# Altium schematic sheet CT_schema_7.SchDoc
size 254 x 194 mm
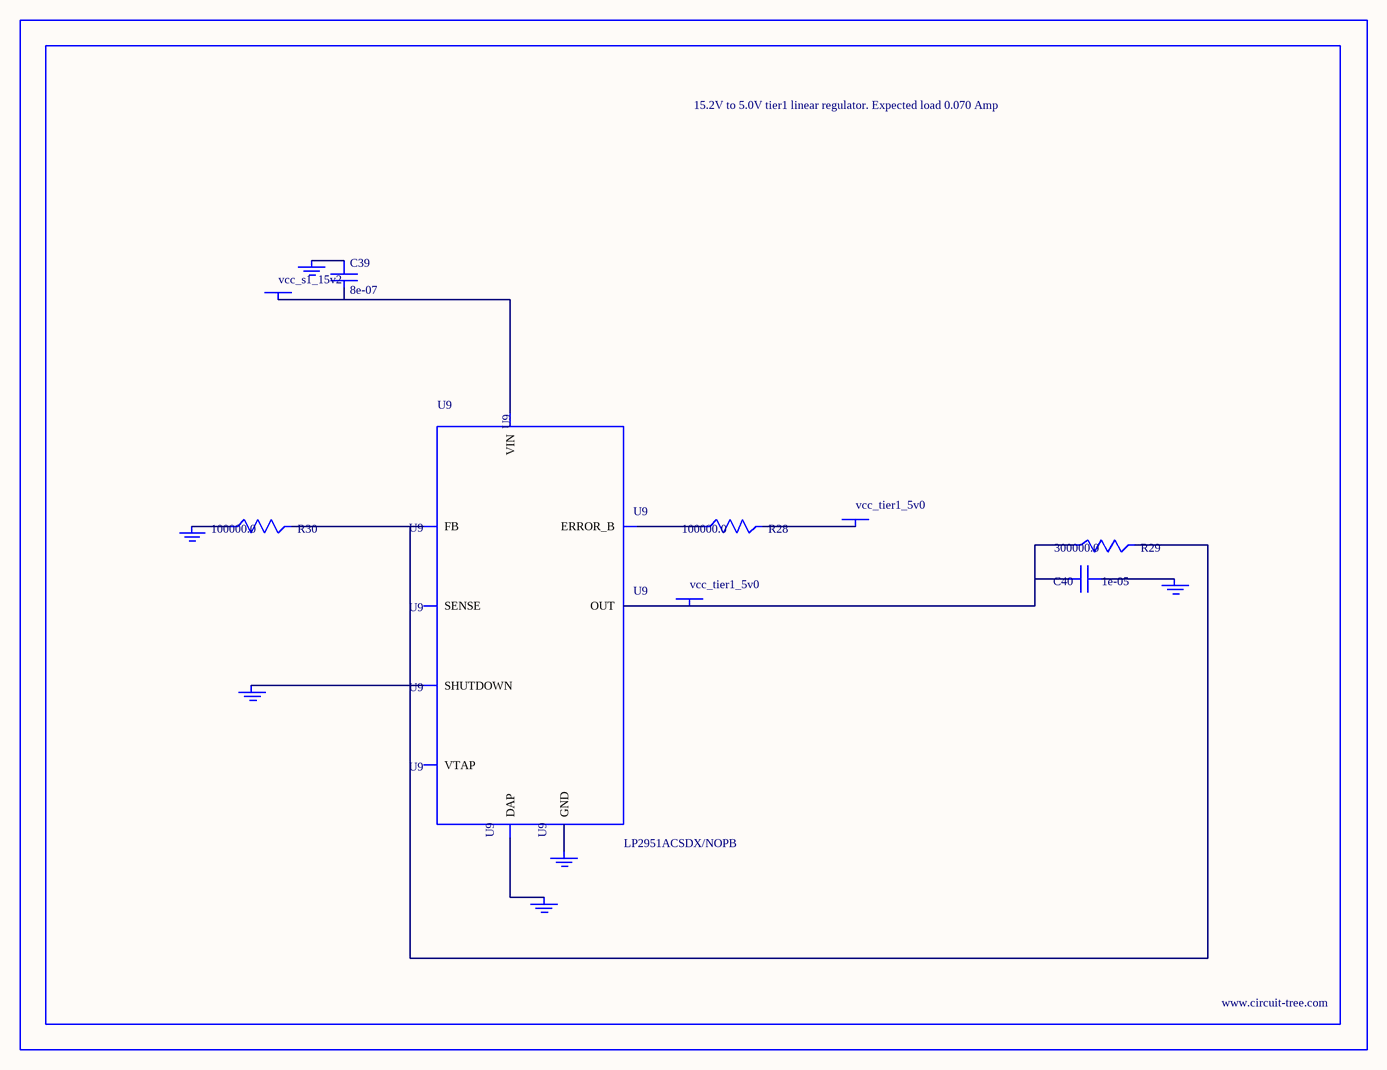
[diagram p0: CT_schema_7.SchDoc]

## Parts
BORDER6  (no value)
C39  8e-07  [R0603]
C40  1e-05  [C1210]
GND_INSTANCE_6_0  (no value)
GND_INSTANCE_6_1  (no value)
GND_INSTANCE_6_2  (no value)
GND_INSTANCE_6_3  (no value)
GND_INSTANCE_6_4  (no value)
GND_INSTANCE_6_5  (no value)
POWER_INSTANCE_6_0  vcc_tier1_5v0
POWER_INSTANCE_6_1  vcc_s1_15v2
POWER_INSTANCE_6_2  vcc_tier1_5v0
R28  100000.0  [R0603]
R29  300000.0  [R0603]
R30  100000.0  [R0603]
U9  LP2951ACSDX/NOPB  [WSON-8]

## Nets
NetC39_1: C39.1 GND_INSTANCE_6_3.0(GND)
NetC39_2: C39.2 POWER_INSTANCE_6_1.0(PWR) U9.8(VIN)
NetC40_1: C40.1 GND_INSTANCE_6_0.0(GND)
NetC40_2: C40.2 POWER_INSTANCE_6_2.0(PWR) R29.1 U9.1(OUT)
NetGND_INSTANCE_6_1_0: GND_INSTANCE_6_1.0(GND) U9.3(SHUTDOWN)
NetGND_INSTANCE_6_2_0: GND_INSTANCE_6_2.0(GND) R30.1
NetGND_INSTANCE_6_4_0: GND_INSTANCE_6_4.0(GND) U9.PAD(DAP)
NetGND_INSTANCE_6_5_0: GND_INSTANCE_6_5.0(GND) U9.4(GND)
NetPOWER_INSTANCE_6_0_0: POWER_INSTANCE_6_0.0(PWR) R28.2
NetR28_1: R28.1 U9.5(ERROR_B)
NetR29_2: R29.2 R30.2 U9.7(FB)

Not connected (* = marked no-connect by the designer): U9 2(SENSE) 6(VTAP)

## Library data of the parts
BORDER6 = BORDER_PAGE6
C39 = C39
C40 = GRM32DR61E106MA12L
GND_INSTANCE_6_0-GND_INSTANCE_6_5 = GND
POWER_INSTANCE_6_0-POWER_INSTANCE_6_2 = PWR
R28 R30 = RC0603JR-07100KL
R29 = RC0603JR-07300KL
